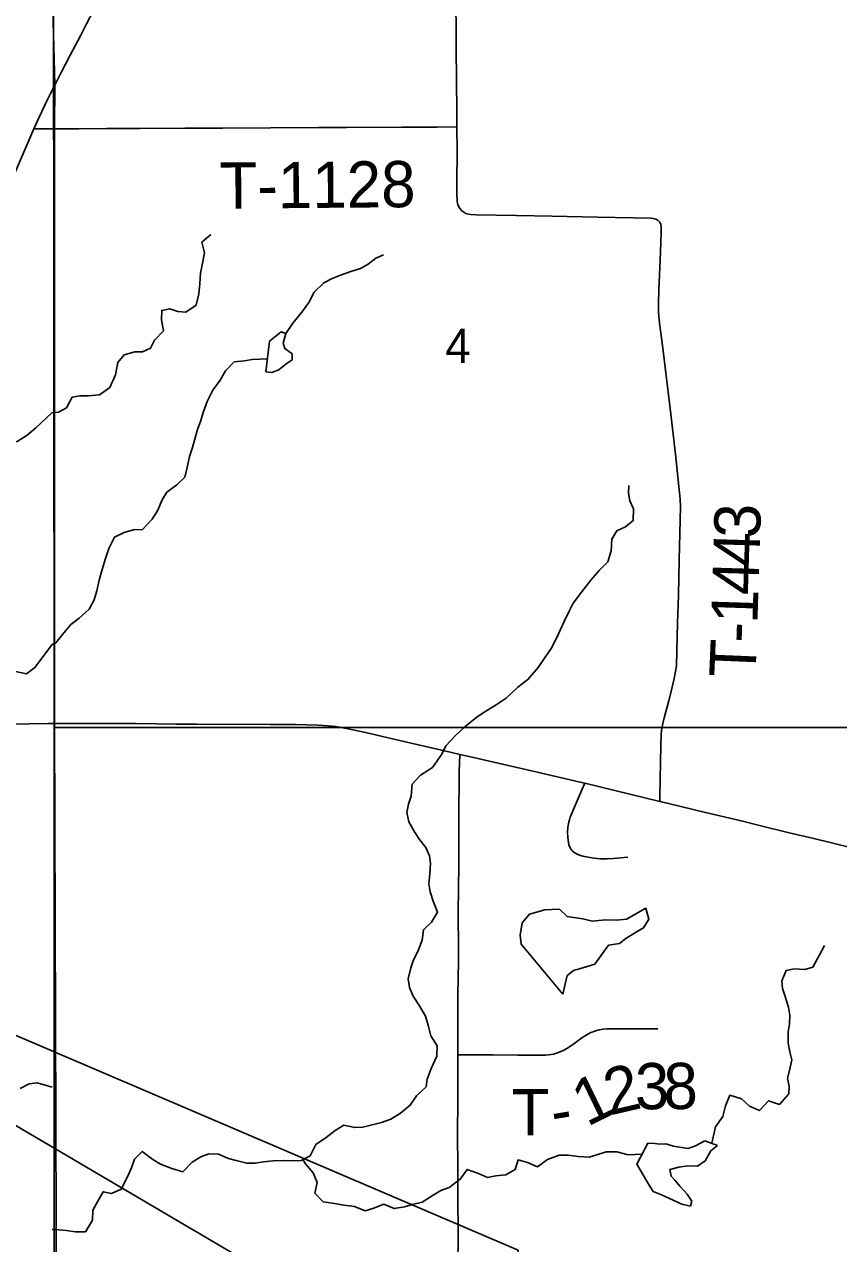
# Model space of a CAD drawing. Extents: x 0 to 70.2, y 0 to 31.4.
# Drawn here: x 6.741 to 7.741, y 16.713 to 18.211 of the extents above; entities that cross this region are included whole.
import ezdxf

# ---------------------------------------------------------------- set-up
doc = ezdxf.new("R2010")
doc.units = 0
for name, color, linetype in [('Default', 7, 'Continuous'), ('GM_X_Minor_Lake', 7, 'Continuous'), ('GM_X_Minor_River', 7, 'Continuous'), ('GM_X_Section', 7, 'Continuous'), ('GM_X_Section_Text', 7, 'Continuous'), ('GM_X_State_Route', 7, 'Continuous'), ('GM_X_Township_Road', 7, 'Continuous'), ('GM_X_Township_Road_Text', 7, 'Continuous'), ('SH_Cut_Line', 7, 'Continuous')]:
    doc.layers.add(name, color=color, linetype=linetype)

msp = doc.modelspace()

# ---------------------------------------------------------------- linework, layer by layer
at = {"layer": 'Default'}
msp.add_lwpolyline([(7.3479, 16.7052), (6.0425, 17.2633), (7.3479, 16.4952)], close=True, dxfattribs=at)
at = {"layer": 'GM_X_Minor_Lake'}
for points in [[(7.0379, 17.7843), (7.0451, 17.7835), (7.0538, 17.7865), (7.0626, 17.7934), (7.0702, 17.7987), (7.0702, 17.8062), (7.0614, 17.8127), (7.0592, 17.8192), (7.0626, 17.8313), (7.0569, 17.8332), (7.0425, 17.8218)], [(7.0425, 17.8218), (7.0379, 17.7843)], [(7.4024, 17.0198), (7.405, 17.0305), (7.4081, 17.0426), (7.4157, 17.0487), (7.427, 17.0521), (7.4418, 17.0566), (7.4585, 17.0798), (7.4722, 17.082), (7.4798, 17.0881), (7.4919, 17.0953), (7.5018, 17.101), (7.5082, 17.112), (7.5044, 17.1253), (7.4809, 17.112), (7.4684, 17.1105), (7.4548, 17.1109), (7.4388, 17.1094), (7.4271, 17.1124), (7.4081, 17.1151), (7.3983, 17.1242), (7.3804, 17.1234), (7.3615, 17.1181), (7.3527, 17.1071), (7.3501, 17.0923), (7.3516, 17.081)], [(7.3516, 17.081), (7.4024, 17.0198)], [(7.5771, 16.8395), (7.5654, 16.8334), (7.5566, 16.83), (7.5483, 16.8315), (7.5384, 16.8331), (7.5289, 16.8357), (7.5217, 16.8354), (7.5157, 16.8361), (7.507, 16.8365), (7.4933, 16.8107), (7.5084, 16.7849), (7.5137, 16.7773), (7.5236, 16.7731), (7.538, 16.7667), (7.5486, 16.7617), (7.5593, 16.7594), (7.5608, 16.7655), (7.5551, 16.7739), (7.5467, 16.7834), (7.5403, 16.791), (7.5358, 16.7963), (7.5339, 16.8042), (7.5452, 16.8073), (7.5562, 16.8088), (7.568, 16.8084), (7.5775, 16.8148), (7.5843, 16.8274), (7.5927, 16.8338)], [(7.5927, 16.8338), (7.5771, 16.8395)]]:
    msp.add_lwpolyline(points, dxfattribs=at)
at = {"layer": 'GM_X_Minor_River'}
for points in [[(6.7753, 17.7337), (6.7833, 17.7348), (6.7933, 17.74), (6.8001, 17.7529), (6.8096, 17.7548), (6.8202, 17.7548), (6.8335, 17.7559), (6.8464, 17.765), (6.8532, 17.7806), (6.8563, 17.7957), (6.8638, 17.8052), (6.8771, 17.8086), (6.8866, 17.8086), (6.8961, 17.8132), (6.901, 17.823), (6.9124, 17.8344), (6.9098, 17.8481), (6.9101, 17.8595), (6.92, 17.8617), (6.9299, 17.8583), (6.9397, 17.8575), (6.9522, 17.8659), (6.9557, 17.8799), (6.9568, 17.8928), (6.9576, 17.9053), (6.9602, 17.9175), (6.9625, 17.9304), (6.9595, 17.9433), (6.9705, 17.9528)], [(7.0626, 17.8313), (7.0709, 17.8438), (7.0819, 17.8575), (7.0907, 17.8692), (7.0971, 17.8821), (7.1093, 17.8935), (7.1195, 17.8988), (7.1297, 17.903), (7.1423, 17.9075), (7.154, 17.9109), (7.1635, 17.9166), (7.173, 17.9238), (7.1825, 17.928)], [(6.7754, 17.4494), (6.7801, 17.4512), (6.7882, 17.4615), (6.7985, 17.4736), (6.8087, 17.4816), (6.8208, 17.4926), (6.8269, 17.504), (6.8303, 17.515), (6.8334, 17.5282), (6.8368, 17.5415), (6.8406, 17.5537), (6.8451, 17.5673), (6.852, 17.581), (6.8641, 17.5867), (6.8766, 17.5905), (6.8861, 17.5901), (6.8983, 17.603), (6.9047, 17.6136), (6.9104, 17.6269), (6.9165, 17.6363), (6.9286, 17.6454), (6.9385, 17.6549), (6.9411, 17.6667), (6.9442, 17.6803), (6.948, 17.691), (6.951, 17.7031), (6.9541, 17.7134), (6.9579, 17.7244), (6.9609, 17.7342), (6.9658, 17.7475), (6.973, 17.7615), (6.9818, 17.774), (6.9882, 17.7854), (6.9992, 17.7964), (7.0118, 17.7976), (7.0212, 17.7991), (7.0399, 17.8002)], [(6.645, 17.6415), (6.6506, 17.6511), (6.6608, 17.653), (6.6719, 17.6563), (6.6821, 17.6604), (6.6939, 17.671), (6.705, 17.6854), (6.7191, 17.6956), (6.7324, 17.6985), (6.745, 17.7064), (6.7556, 17.7155), (6.7753, 17.7337)], [(7.4474, 17.54), (7.458, 17.5507), (7.4618, 17.5643), (7.4629, 17.5784), (7.469, 17.589), (7.4796, 17.5939), (7.4891, 17.6015), (7.4895, 17.6159), (7.485, 17.6258), (7.4831, 17.6353), (7.4835, 17.6447)], [(6.7756, 16.7307), (6.7795, 16.7307), (6.7932, 16.7292), (6.8042, 16.7276), (6.8163, 16.7276), (6.825, 16.742), (6.8254, 16.7542), (6.8315, 16.7656), (6.8383, 16.7769), (6.8482, 16.7747), (6.8603, 16.78), (6.8671, 16.7936), (6.8728, 16.8065), (6.8766, 16.8168), (6.8861, 16.8266), (6.899, 16.8164), (6.9085, 16.8107), (6.9225, 16.8054), (6.9358, 16.8016), (6.9476, 16.8133), (6.9582, 16.8197), (6.9677, 16.8235), (6.9798, 16.8232), (6.9919, 16.8178), (7.0014, 16.8152), (7.0147, 16.8121), (7.0249, 16.8121), (7.0352, 16.8136), (7.0469, 16.8151), (7.0594, 16.8155), (7.0716, 16.8148), (7.0814, 16.8155), (7.0924, 16.8212), (7.0993, 16.8352), (7.1118, 16.8436), (7.1232, 16.8523), (7.1338, 16.8587), (7.1471, 16.8557), (7.1569, 16.8564), (7.1668, 16.8587), (7.1801, 16.8621), (7.1914, 16.8663), (7.2032, 16.8735), (7.2153, 16.8833), (7.2229, 16.8947), (7.2347, 16.9057), (7.2362, 16.9152), (7.2408, 16.9285), (7.248, 16.9437), (7.2484, 16.9562), (7.2404, 16.9683), (7.2374, 16.9816), (7.234, 16.9926), (7.2264, 17.0055), (7.2188, 17.0173), (7.2143, 17.0279), (7.2128, 17.0385), (7.2158, 17.0522), (7.2192, 17.0617), (7.2245, 17.0719), (7.2298, 17.086), (7.2314, 17.0989), (7.2412, 17.108), (7.2488, 17.1205), (7.2435, 17.1341), (7.2397, 17.1455), (7.2382, 17.1554), (7.2394, 17.1675), (7.2401, 17.1801), (7.239, 17.1895), (7.2345, 17.1998), (7.2265, 17.2097), (7.2204, 17.2192), (7.2136, 17.2313), (7.211, 17.2427), (7.2132, 17.2529), (7.2163, 17.2628), (7.2174, 17.2776), (7.2277, 17.2886), (7.2425, 17.2981), (7.2539, 17.3144), (7.2588, 17.3246), (7.2706, 17.3375), (7.2823, 17.3481), (7.2975, 17.3603), (7.3081, 17.3675), (7.3206, 17.375), (7.3328, 17.3834), (7.3472, 17.3967), (7.3597, 17.4061), (7.3722, 17.4209), (7.381, 17.4338), (7.3882, 17.4444), (7.3954, 17.4577), (7.3996, 17.4676), (7.4041, 17.4775), (7.4102, 17.49), (7.4151, 17.4998), (7.4254, 17.5135), (7.4368, 17.5283), (7.4474, 17.54)], [(6.7303, 17.4161), (6.7439, 17.413), (6.7542, 17.4209), (6.7754, 17.4494)], [(7.5854, 16.8365), (7.59, 16.8569), (7.5991, 16.8695), (7.6022, 16.8827), (7.6075, 16.8956), (7.6219, 16.8911), (7.6317, 16.882), (7.6439, 16.8766), (7.6553, 16.8888), (7.6685, 16.8842), (7.6803, 16.8971), (7.6807, 16.9066), (7.6784, 16.9161), (7.6818, 16.9297), (7.6837, 16.9392), (7.6815, 16.9487), (7.6792, 16.9593), (7.6792, 16.9734), (7.6811, 16.9832), (7.6815, 16.9939), (7.6796, 17.0037), (7.6758, 17.017), (7.6724, 17.0265), (7.6716, 17.036), (7.677, 17.0489), (7.6868, 17.0508), (7.6997, 17.05), (7.7096, 17.0527), (7.7175, 17.0671), (7.724, 17.0796)], [(6.7362, 16.904), (6.7472, 16.9097), (6.7571, 16.9108), (6.7756, 16.9053)], [(7.0835, 16.8166), (7.0864, 16.8113), (7.0962, 16.8003), (7.1011, 16.7882), (7.0981, 16.7753), (7.1083, 16.7646), (7.1224, 16.7624), (7.1337, 16.7605), (7.1466, 16.7589), (7.1599, 16.7536), (7.1694, 16.7563), (7.1827, 16.7616), (7.1956, 16.7562), (7.2081, 16.7585), (7.2179, 16.7612), (7.2297, 16.7642), (7.2433, 16.7729), (7.2528, 16.7786), (7.2631, 16.782), (7.2764, 16.7926), (7.2851, 16.8044), (7.2991, 16.7994), (7.3101, 16.7945), (7.3203, 16.7964), (7.3325, 16.7979), (7.3442, 16.8043), (7.3477, 16.8161), (7.3594, 16.8127), (7.3715, 16.8074), (7.3837, 16.8165), (7.3981, 16.8218), (7.4091, 16.8218), (7.4216, 16.8202), (7.4349, 16.8195), (7.4455, 16.8229), (7.4558, 16.8259), (7.469, 16.8259), (7.4827, 16.8225), (7.4999, 16.8231)]]:
    msp.add_lwpolyline(points, dxfattribs=at)
at = {"layer": 'GM_X_Section'}
for points in [[(7.7683, 18.3114), (7.7735, 17.3473), (6.7779, 17.3473), (6.7772, 18.3092)], [(6.7779, 17.3473), (7.7735, 17.3473), (7.7683, 16.3298), (6.7778, 16.3386)]]:
    msp.add_lwpolyline(points, close=True, dxfattribs=at)
at = {"layer": 'GM_X_Section_Text'}
for points in [[(6.7742, 18.3058), (6.7786, 18.1369), (6.7782, 18.0833), (6.7784, 17.3526), (6.7807, 16.6175)], [(6.7807, 16.6175), (6.7784, 17.3526), (6.7782, 18.0833), (6.7786, 18.1369), (6.7742, 18.3058)]]:
    msp.add_lwpolyline(points, dxfattribs=at)
at = {"layer": 'GM_X_State_Route'}
for points in [[(6.7788, 18.1363), (6.7862, 18.1511), (6.7978, 18.173), (6.8108, 18.1977), (6.8177, 18.2116), (6.8263, 18.2281), (6.8307, 18.2363), (6.8365, 18.2472), (6.8453, 18.2636), (6.8541, 18.28), (6.8675, 18.3046), (6.8678, 18.3052)], [(6.7179, 18.0009), (6.7531, 18.0827), (6.7598, 18.0976), (6.7691, 18.1171), (6.7732, 18.1251), (6.7788, 18.1363)], [(6.2538, 17.3478), (6.2568, 17.3479), (6.2885, 17.3482), (6.363, 17.3484), (6.4126, 17.3481), (6.4436, 17.3481), (6.4839, 17.3484), (6.518, 17.3486), (6.5397, 17.3487), (6.5583, 17.3487), (6.5831, 17.3489), (6.6048, 17.3493), (6.6235, 17.3497), (6.6421, 17.35), (6.6978, 17.3513), (6.7473, 17.3518), (6.7704, 17.352), (6.7786, 17.3521)], [(6.7786, 17.3521), (6.7854, 17.3521), (6.8382, 17.3522), (6.8786, 17.352), (6.9283, 17.3513), (6.9532, 17.3513), (7.0433, 17.3511), (7.0743, 17.3509), (7.1023, 17.3502), (7.1146, 17.3495), (7.1238, 17.3484), (7.1391, 17.3458), (7.1604, 17.3413), (7.1936, 17.3334), (7.2269, 17.3255), (7.2571, 17.3184), (7.2763, 17.3141), (7.2877, 17.3115), (7.3693, 17.2928), (7.4237, 17.2802), (7.4297, 17.2788), (7.4479, 17.2744), (7.5216, 17.2565), (7.5325, 17.2539), (7.5778, 17.2428), (7.6201, 17.2329), (7.6472, 17.2261), (7.6804, 17.2179), (7.7107, 17.2107), (7.756, 17.2)]]:
    msp.add_lwpolyline(points, dxfattribs=at)
at = {"layer": 'GM_X_Township_Road'}
for points in [[(7.2726, 18.0852), (7.2724, 18.1046), (7.272, 18.1418), (7.2718, 18.1824), (7.2713, 18.2573), (7.2707, 18.3149)], [(6.7531, 18.0827), (6.7616, 18.0827), (6.773, 18.0826), (6.7784, 18.0827)], [(6.7784, 18.0827), (6.8083, 18.0826), (6.8424, 18.0832), (6.8827, 18.0831), (6.9384, 18.0834), (6.9849, 18.0833), (7.0438, 18.084), (7.1027, 18.0843), (7.1368, 18.0844), (7.205, 18.0847), (7.2484, 18.0847), (7.2726, 18.0852)], [(7.5216, 17.2565), (7.5217, 17.263), (7.5228, 17.3253), (7.5233, 17.3377), (7.5239, 17.3439), (7.5248, 17.35), (7.527, 17.3591), (7.5326, 17.3801), (7.5366, 17.3952), (7.5392, 17.4073), (7.541, 17.4164), (7.542, 17.4231), (7.5426, 17.4413), (7.5433, 17.4755), (7.5445, 17.5097), (7.5456, 17.5532), (7.5469, 17.6185), (7.5465, 17.6279), (7.545, 17.6434), (7.5411, 17.6832), (7.5344, 17.7391), (7.5248, 17.8163), (7.5212, 17.8441), (7.5202, 17.8572), (7.5199, 17.869), (7.5205, 17.8845), (7.5224, 17.9311), (7.5232, 17.956), (7.5233, 17.9623), (7.5228, 17.9653), (7.5215, 17.9681), (7.5193, 17.9703), (7.5166, 17.9718), (7.5136, 17.9726), (7.5105, 17.9729), (7.4888, 17.9732), (7.4453, 17.9742), (7.3893, 17.9753), (7.3458, 17.9763), (7.296, 17.9772), (7.2897, 17.9775), (7.2866, 17.978), (7.2836, 17.9788), (7.2809, 17.9801), (7.2784, 17.9819), (7.2764, 17.9842), (7.2748, 17.9869), (7.2737, 17.9898), (7.273, 17.9928), (7.2727, 17.9959), (7.2725, 18.0021), (7.2726, 18.0177), (7.2728, 18.055), (7.2726, 18.0852)], [(7.2737, 16.9453), (7.2736, 16.9593), (7.2736, 16.9913), (7.2738, 17.0193), (7.2743, 17.0598), (7.2745, 17.0754), (7.2742, 17.119), (7.2745, 17.1502), (7.2747, 17.1783), (7.275, 17.2125), (7.275, 17.2343), (7.2754, 17.2936), (7.2757, 17.3029), (7.2763, 17.3141)], [(7.4826, 17.188), (7.4648, 17.1864), (7.457, 17.1859), (7.4485, 17.1861), (7.4412, 17.1868), (7.4337, 17.188), (7.427, 17.1892), (7.423, 17.1903), (7.42, 17.1915), (7.4172, 17.1931), (7.4148, 17.195), (7.4127, 17.1974), (7.4112, 17.2001), (7.4101, 17.203), (7.4094, 17.2061), (7.4087, 17.2123), (7.4085, 17.2186), (7.4089, 17.2248), (7.4099, 17.231), (7.4107, 17.234), (7.4117, 17.237), (7.4151, 17.2457), (7.4228, 17.2628), (7.4265, 17.2714), (7.4297, 17.2788)], [(7.2737, 16.9453), (7.3163, 16.9451), (7.3475, 16.9449), (7.3694, 16.9446), (7.3819, 16.9448), (7.3881, 16.9454), (7.3911, 16.9461), (7.3971, 16.948), (7.4028, 16.9505), (7.4083, 16.9535), (7.416, 16.9588), (7.4261, 16.9662), (7.4314, 16.9695), (7.4341, 16.971), (7.437, 16.9724), (7.4399, 16.9735), (7.4428, 16.9746), (7.4471, 16.9758), (7.4522, 16.9766), (7.457, 16.977), (7.4645, 16.9769), (7.5083, 16.9771), (7.5192, 16.9772)], [(7.2736, 16.6845), (7.2739, 16.7249), (7.2739, 16.7373), (7.2736, 16.7589), (7.2735, 16.7776), (7.2736, 16.79), (7.2738, 16.7993), (7.2735, 16.8117), (7.2737, 16.8179), (7.2736, 16.821), (7.2733, 16.8335), (7.2732, 16.8552), (7.2736, 16.8831), (7.2737, 16.9421), (7.2737, 16.9453)]]:
    msp.add_lwpolyline(points, dxfattribs=at)
at = {"layer": 'SH_Cut_Line'}
for points in [[(6.7807, 16.6175), (6.7784, 17.3526), (6.7782, 18.0833), (6.7786, 18.1369), (6.7742, 18.3058)], [(6.7742, 18.3058), (6.7786, 18.1369), (6.7782, 18.0833), (6.7784, 17.3526), (6.7807, 16.6175)]]:
    msp.add_lwpolyline(points, dxfattribs=at)

# ---------------------------------------------------------------- texts
at = {"layer": 'GM_X_Section_Text'}
msp.add_text('4', height=0.0419, rotation=0, dxfattribs=at).set_placement((7.2581, 17.7952))
at = {"layer": 'GM_X_Township_Road_Text'}
for s, height, rotation, p in [('T-1128', 0.05682, 0.4687, (6.9812, 17.9845)), ('3', 0.0568, 88.2609, (7.6447, 17.5792)), ('4', 0.0568, 88.2575, (7.6437, 17.5443)), ('4', 0.0568, 88.2506, (7.6426, 17.5093)), ('1', 0.0568, 88.2229, (7.6415, 17.4743)), ('-', 0.0568, 88.1323, (7.6408, 17.4508)), ('T', 0.0568, 87.5951, (7.639, 17.4078)), ('2', 0.0568, 13.231, (7.4605, 16.8706)), ('3', 0.0568, 0.3331, (7.4912, 16.8782)), ('8', 0.0568, 0.3856, (7.5263, 16.8784)), ('1', 0.0568, 25.9225, (7.4321, 16.8564)), ('T', 0.0568, 0.2829, (7.3398, 16.8462)), ('-', 0.0568, 9.2702, (7.392, 16.8472))]:
    msp.add_text(s, height=height, rotation=rotation, dxfattribs=at).set_placement(p)

doc.saveas('drawing.dxf')
